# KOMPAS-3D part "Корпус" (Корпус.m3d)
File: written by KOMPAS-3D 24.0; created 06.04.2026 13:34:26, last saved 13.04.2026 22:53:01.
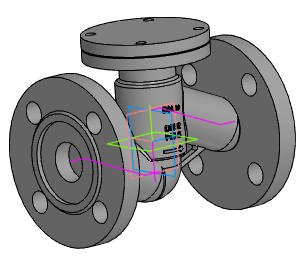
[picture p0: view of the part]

Document properties: Автор: R2D2; Полное имя файла: E:\Работа\Зайцев\VSO3131M-F-S Клапан запорный DN.ru Ду15-100 Ру40\DN32\исходные материалы\Корпус.m3d

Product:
- Body: Труба / Нестандартная труба / L = 89.9 мм  | qty 1
    Материал: Нестандартная труба (density 7856 kg/m3)
    Масса: 7.041936
    Раздел спецификации: Детали
    Примечание: 0,98 кг
    additional columns: Pipeline; 0.042; 0; 0; 0.002; 0.08987; true; 0.04
- Body: Труба / Нестандартная труба / L = 111.7 мм  | qty 1
    Материал: Нестандартная труба (density 7856 kg/m3)
    Масса: 7.041936
    Раздел спецификации: Детали
    Примечание: 1,22 кг
    additional columns: Pipeline; 0.042; 0; 0; 0.002; 0.11172; true; 0.04
- Body: Тело 4  | qty 1
    Материал: Нестандартная труба (density 7856 kg/m3)
    Масса: 7.041936
- Body: Тело 5  | qty 1
    Материал: Нестандартная труба (density 7856 kg/m3)
    Масса: 7.041936
- Body: Тело 8  | qty 1
    Материал: Нестандартная труба (density 7856 kg/m3)
    Масса: 7.041936
- Body: Тело 9  | qty 1
    Материал: Нестандартная труба (density 7856 kg/m3)
    Масса: 7.041936
- Part/product: Корпус
    Масса: 6.9

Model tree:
1. Труба
2. Труба:1  (labels: {F703FF30-5BE6-4673-A7F1-8EDA1BE1E2D1}; SHAPEOBJECT3D_ATTR_BUTT; SHAPEOBJECT3D_ATTR_VALID; SHAPEOBJECT3D_ATTR_BUTT_AREA)
     PIPE_R = 7
3. Труба:2  (labels: {F703FF30-5BE6-4673-A7F1-8EDA1BE1E2D1}; SHAPEOBJECT3D_ATTR_BUTT; SHAPEOBJECT3D_ATTR_VALID; SHAPEOBJECT3D_ATTR_BUTT_AREA)
     PIPE_R = 7
4. Колонна
5. Элемент выдавливания:1
     Смещение 1 = -1; Смещение 2 = -5
6. Скругление:17  (with: Ребро.Элемент выдавливания:1)
     Радиус = 1
7. Скругление:18  (with: Ребро.Элемент выдавливания:1)
8. Скругление:24  (with: Ребро.Элемент выдавливания:1)
     Радиус = 1.5
9. Элемент выдавливания:2
     Расстояние 1 = 6
10. Скругление:19  (with: Ребро.Элемент выдавливания:2)
     Радиус = 2
11. Эскиз:4  (with: Грань.Элемент выдавливания:1)
12. Элемент выдавливания:3
     Расстояние 1 = 17.5
13. Скругление:21  (with: Ребро.Элемент выдавливания:3)
14. ОТЛИВКА
15. Скругление:6  (with: Грань.Элемент выдавливания:1)
     Радиус = 2
16. Элемент выдавливания:6  (with: Грань.Элемент выдавливания:1)
     Смещение 1 = 4
17. ЛЕЙБЛ
18. Элемент выдавливания:7  (with: Грань.Элемент выдавливания:1)
     Расстояние 1 = 26.9988; Смещение 1 = 1
19. Фланец верх  (with: Ребро.Элемент выдавливания:3)
20. Элемент вращения:2
     Угол 1 = 360
21. Эскиз:12  (with: Грань.Элемент вращения:2)
22. Элемент выдавливания:9  (with: Грань.Элемент вращения:2)
     Расстояние 2 = 20
23. Массив по концентрической сетке:1  (with: Элемент выдавливания:9, Эскиз:12, Грань.Элемент вращения:2)  (4 pattern instances)
     Шаг 2 = 360
24. Фланец
25. Элемент вращения:1
     Угол 1 = 360
26. отвертие во фланце  (with: Грань.Элемент вращения:1)
27. Элемент выдавливания:8
28. Массив по концентрической сетке:2  (with: Элемент выдавливания:8, Эскиз:10, Грань.Элемент вращения:1)  (4 pattern instances)
     Шаг 2 = 360
29. Зеркальный массив:1
30. Экземпляр ( 1 )
31. Экземпляр ( 2 )  (with: Элемент вращения:1, Массив по концентрической сетке:2, Экземпляр ( 1 ), Элемент выдавливания:8)
32. Экземпляр ( 3 )  (with: Элемент выдавливания:8)
33. Экземпляр ( 4 )  (with: Элемент выдавливания:8)
34. Скругление:25  (with: Ребро.Элемент вращения:2)
     Радиус = 2

Expressions: DS/2+3; D1/2; DN/2; D/2; DS-v977*4; LL/2; D1-v1234*2
Referenced files in C:\Program Files\ASCON\KOMPAS-3D v24\Libs\Pipeline\: StylesTemplate.a3d, TemplateHPH, InsulationStylesTemplate.a3d, Insulation
Referenced files in C:\Program Files\ASCON\KOMPAS-3D v24\Templates\: Констр. чертеж А3 гориз. перв. лист.cdt
Referenced files in E:\Работа\Зайцев\VSO3131M-F-S Клапан запорный DN.ru Ду15-100 Ру40\DN20\исходные материалы\: 
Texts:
  Отводы ГОСТ 17375-2001
  Констр. чертеж А3 гориз. перв. лист.cdt
  GOST 26.020 Pr3
  var3D
  GOST 2.304 type A
  смещение колонны вниз
  LL-10
  DN+10
  Труба / Нестандартная труба / L = %s мм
